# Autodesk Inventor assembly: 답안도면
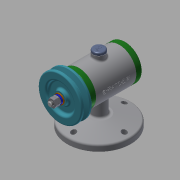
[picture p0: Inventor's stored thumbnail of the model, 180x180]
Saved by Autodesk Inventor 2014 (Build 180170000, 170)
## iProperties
Created: 2018-12
Part Number: 답안도면
Document SubType Name: Assembly
Designer: kh
Author: kh
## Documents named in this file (15)
- C:\Users\kh\Desktop\481207V1020\답안도면.iam
- C:\Users\kh\Desktop\481207V1020\본체.ipt
- C:\Users\kh\Desktop\481207V1020\V벨트풀리.ipt
- C:\Users\kh\Desktop\481207V1020\고무캡.ipt
- C:\Users\kh\Desktop\481207V1020\너트 M8.ipt
- 너트 M8.ipt
- C:\Users\kh\Desktop\481207V1020\뒤커버.ipt
- C:\Users\kh\Desktop\481207V1020\베어링 15 x 32 x 9.ipt
- C:\Users\kh\Desktop\481207V1020\볼트 M4 x 12.ipt
- C:\Users\kh\Desktop\481207V1020\스프링와셔 8.ipt
- C:\Users\kh\Desktop\481207V1020\앞커버.ipt
- C:\Users\kh\Desktop\481207V1020\오일 실 15 25 7.ipt
- C:\Users\kh\Desktop\481207V1020\와셔 8x17.ipt
- C:\Users\kh\Desktop\481207V1020\축.ipt
- C:\Users\kh\Desktop\481207V1020\키 3 x 3 x 12.ipt
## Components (2 placed, 2 different names)
1. V벨트풀리:1 — Insert:14, Angle:3, Insert:15
2. 고무캡:1 — Insert:19
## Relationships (4: Insert 3, Angle 1)
- Insert:14: V벨트풀리:1
- Angle:3: V벨트풀리:1
- Insert:15: V벨트풀리:1
- Insert:19: 고무캡:1
